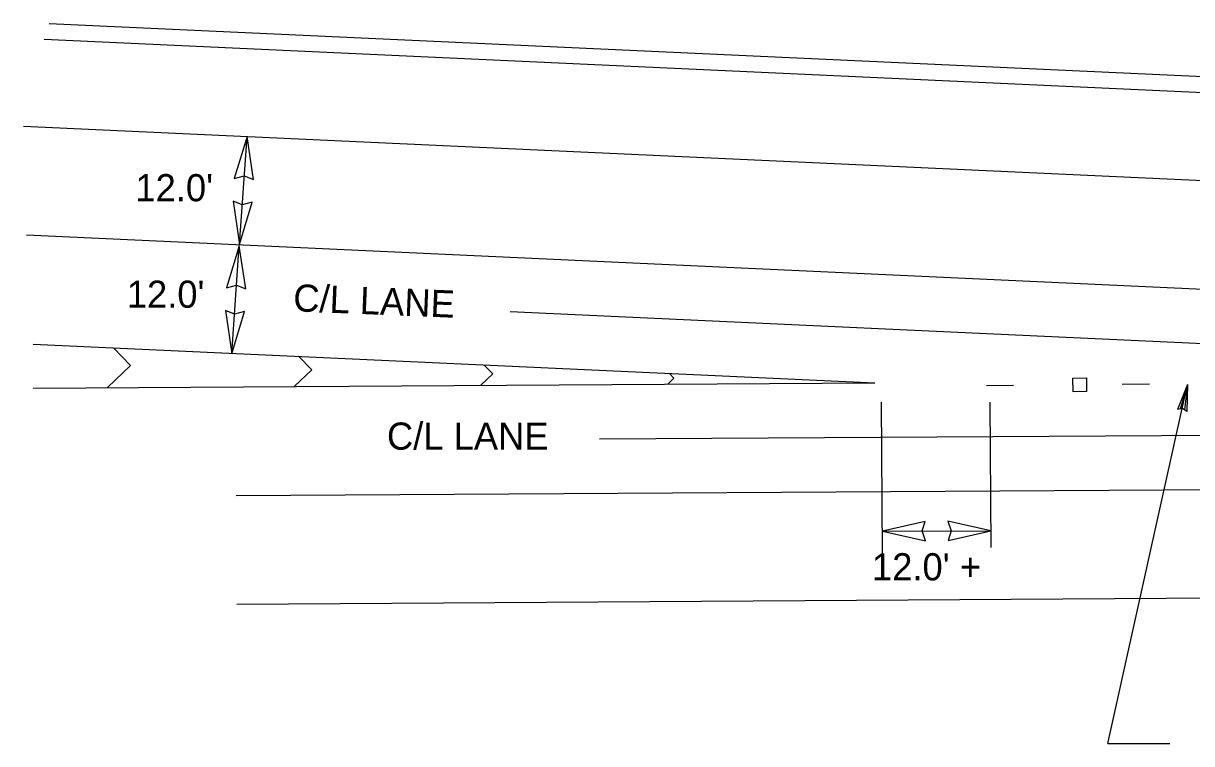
# Model space of a CAD drawing. Extents: x 538465 to 539103, y 1527987 to 1528392.
# Drawn here: x 538547.6 to 538676.5, y 1528236.5 to 1528316.1 of the extents above; entities that cross this region are included whole.
import ezdxf

# ---------------------------------------------------------------- set-up
doc = ezdxf.new("R2010")
doc.units = 0
for name, color, linetype in [('CL_dp', 7, 'Continuous'), ('Default', 7, 'Continuous'), ('DimLines_dp', 7, 'Continuous'), ('PMStripe6W(10-30)', 7, 'Continuous'), ('TextLabel', 7, 'Continuous')]:
    doc.layers.add(name, color=color, linetype=linetype)

msp = doc.modelspace()

# ---------------------------------------------------------------- linework, layer by layer
at = {"layer": 'CL_dp'}
for p, q in [((538601.29, 1528284.26), (538730.57, 1528278.29)), ((538611.16, 1528270.2), (538818.07, 1528271.49))]:
    msp.add_line(p, q, dxfattribs=at)
at = {"layer": 'Default'}
for p, q in [((538550.39, 1528316.09), (538853.15, 1528302.11)), ((538549.84, 1528314.35), (538852.95, 1528300.36)), ((538547.55, 1528304.74), (538858.35, 1528290.39)), ((538547.91, 1528292.72), (538858.28, 1528278.39)), ((538548.64, 1528280.68), (538641.55, 1528276.39)), ((538557.49, 1528280.27), (538559.38, 1528278.29)), ((538577.94, 1528279.33), (538579.38, 1528277.83)), ((538556.85, 1528275.87), (538559.38, 1528278.29)), ((538577.46, 1528276), (538579.38, 1528277.83)), ((538598.07, 1528276.12), (538599.37, 1528277.37)), ((538598.4, 1528278.39), (538599.37, 1528277.37)), ((538618.86, 1528277.44), (538619.37, 1528276.91)), ((538548.64, 1528275.82), (538641.55, 1528276.39)), ((538618.68, 1528276.25), (538619.37, 1528276.91)), ((538656.86, 1528276.09), (538653.86, 1528276.06)), ((538671.86, 1528276.25), (538668.86, 1528276.22))]:
    msp.add_line(p, q, dxfattribs=at)
msp.add_lwpolyline([(538663.4, 1528276.91), (538664.9, 1528276.93), (538664.92, 1528275.43), (538663.42, 1528275.41)], close=True, dxfattribs=at)
at = {"layer": 'DimLines_dp'}
for p, q in [((538572.24, 1528303.61), (538570.84, 1528298.95)), ((538571.41, 1528291.67), (538572.24, 1528303.61)), ((538572.95, 1528298.84), (538572.24, 1528303.61)), ((538570.84, 1528298.95), (538571.94, 1528299.25)), ((538571.94, 1528299.25), (538572.95, 1528298.84)), ((538571.72, 1528296.04), (538570.7, 1528296.45)), ((538570.7, 1528296.45), (538571.41, 1528291.67)), ((538571.41, 1528291.67), (538572.82, 1528296.34)), ((538572.82, 1528296.34), (538571.72, 1528296.04)), ((538571.39, 1528291.53), (538569.99, 1528286.87)), ((538570.56, 1528279.59), (538571.39, 1528291.53)), ((538572.1, 1528286.76), (538571.39, 1528291.53)), ((538569.99, 1528286.87), (538571.09, 1528287.17)), ((538571.09, 1528287.17), (538572.1, 1528286.76)), ((538570.86, 1528283.96), (538569.85, 1528284.37)), ((538569.85, 1528284.37), (538570.56, 1528279.59)), ((538570.56, 1528279.59), (538571.97, 1528284.26)), ((538571.97, 1528284.26), (538570.86, 1528283.96)), ((538667.25, 1528236.55), (538676.06, 1528276.19)), ((538676.06, 1528276.19), (538674.97, 1528273.44)), ((538676.06, 1528276.19), (538675.26, 1528273.5)), ((538676.06, 1528276.19), (538675.74, 1528273.4)), ((538676.06, 1528276.19), (538675.98, 1528273.23)), ((538642.39, 1528257.58), (538642.29, 1528274.27)), ((538654.39, 1528258.2), (538654.29, 1528274.27)), ((538675.52, 1528273.55), (538674.97, 1528273.44)), ((538675.98, 1528273.23), (538675.52, 1528273.55)), ((538647.1, 1528261.08), (538642.39, 1528260.03)), ((538646.76, 1528260.04), (538647.1, 1528261.08)), ((538654.36, 1528260.05), (538649.6, 1528261.12)), ((538649.6, 1528261.12), (538649.98, 1528260.04)), ((538642.39, 1528260.03), (538654.36, 1528260.05)), ((538642.39, 1528260.03), (538647.14, 1528258.96)), ((538647.14, 1528258.96), (538646.76, 1528260.04)), ((538649.65, 1528259), (538654.36, 1528260.05)), ((538649.98, 1528260.04), (538649.65, 1528259)), ((538667.25, 1528236.55), (538674.11, 1528236.55))]:
    msp.add_line(p, q, dxfattribs=at)
at = {"layer": 'PMStripe6W(10-30)'}
for p, q in [((538571.06, 1528263.95), (539020.96, 1528266.76)), ((538571.13, 1528251.96), (539021.04, 1528254.76))]:
    msp.add_line(p, q, dxfattribs=at)

# ---------------------------------------------------------------- texts
at = {"layer": 'DimLines_dp'}
for s, p in [("12.0'", (538559.92, 1528296.44)), ("12.0'", (538558.97, 1528284.68)), ("12.0' +", (538641.23, 1528254.58))]:
    msp.add_text(s, height=3, dxfattribs=at).set_placement(p)
at = {"layer": 'TextLabel'}
msp.add_text('C/L LANE', height=3, rotation=357.6799, dxfattribs=at).set_placement((538577.3, 1528284.3))
msp.add_text('C/L LANE', height=3, dxfattribs=at).set_placement((538587.69, 1528269.01))

doc.saveas('drawing.dxf')
